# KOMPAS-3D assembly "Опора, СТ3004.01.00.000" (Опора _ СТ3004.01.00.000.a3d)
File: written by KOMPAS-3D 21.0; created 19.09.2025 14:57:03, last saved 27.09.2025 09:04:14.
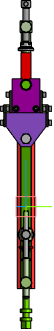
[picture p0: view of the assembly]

Document properties: Полное имя файла: C:\Users\Lutik\Yandex.Disk\Документы\Новая папка\Стапель №2\Стапель _ СТ3004.00.00.000\Опора _ СТ3004.01.00.000\3D\Опора _ СТ3004.01.00.000.a3d; Автор: 1

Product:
- Part/product: Опора  | designation СТ3004.01.00.000
    Масса: 19.478308
    Форматы листов документа: A3
  - Component [assembly]: Кронштейн  | designation СТ3004.01.01.000  | pos. 2  | Масса: 11.762936; Форматы листов документа: A2; source file: ..\2D\Кронштейн _ СТ3004.01.01.000\Кронштейн _ СТ3004.01.01.000.cdw, Кронштейн _ СТ3004.01.01.000\Кронштейн _ СТ3004.01.01.000.a3d
  - Component [assembly]: Кронштейн  | designation СТ3004.01.02.000  | pos. 3  | Масса: 5.184451; Форматы листов документа: A3; source file: ..\2D\Кронштейн _ СТ3004.01.02.000\Кронштейн _ СТ3004.01.02.000.cdw, Кронштейн _ СТ3004.01.02.000\Кронштейн _ СТ3004.01.02.000.a3d
  - Component [detail]: Винт  | designation СТ3003.01.00.001  | pos. 4  | Материал: Круг$d30 ГОСТ 2590-2006;Ст3сп ГОСТ 535-2005$ (density 7850 kg/m3); Масса: 0.303608; Форматы листов документа: A4; additional columns: 120; source file: ..\..\..\Стапель _ СТ3003.00.00.000\Опора _ СТ3003.01.00.000\2D\Винт _ СТ3003.01.00.001.cdw, ..\..\..\Стапель _ СТ3003.00.00.000\Опора _ СТ3003.01.00.000\3D\Винт _ СТ3003.01.00.001.m3d
  - Component [assembly]: Струбцина  | designation СТ3003.01.03.000  | pos. 1  | Масса: 1.103282; Раздел спецификации: Сборочные единицы; Форматы листов документа: A3; source file: ..\..\..\Стапель _ СТ3003.00.00.000\Опора _ СТ3003.01.00.000\2D\Струбцина _ СТ3003.01.03.000\Струбцина _ СТ3003.01.03.000.cdw, ..\..\..\Стапель _ СТ3003.00.00.000\Опора _ СТ3003.01.00.000\3D\Струбцина _ СТ3003.01.03.000\Струбцина _ СТ3003.01.03.000.a3d
  - Component [assembly]: Струбцина  | designation СТ3003.01.03.000-02  | pos. 1  | Масса: 1.075052; Форматы листов документа: A3; source file: ..\..\..\Стапель _ СТ3003.00.00.000\Опора _ СТ3003.01.00.000\2D\Струбцина _ СТ3003.01.03.000\Струбцина _ СТ3003.01.03.000.cdw, ..\..\..\Стапель _ СТ3003.00.00.000\Опора _ СТ3003.01.00.000\3D\Струбцина _ СТ3003.01.03.000\Струбцина _ СТ3003.01.03.000.a3d
  - Component [standard]: Винт с шестигранной головкой ГОСТ Р ИСО 4017-М16 x 45-5.8-A2P  | pos. 5  | Материал: Сталь (density 1000 kg/m3); Масса: 0.01392; Раздел спецификации: Стандартные изделия; Рассекать на разрезах: no; additional columns: ГОСТ Р ИСО 4017-2013; М16 x 45 - 5.8 - A2P

Referenced files in C:\Users\1\Yandex.Disk\Документы\Новая папка\Стапель №2\Стапель _ СТ3003.00.00.000\Опора _ СТ3003.01.00.000\3D\Струбцина _ СТ3003.01.03.000\: Струбцина _ СТ3003.01.03.000.a3d
Referenced files in C:\Users\1\Yandex.Disk\Документы\Новая папка\Стапель №2\Стапель _ СТ3004.00.00.000\Опора _ СТ3004.01.00.000\3D\Кронштейн _ СТ3004.01.02.000\: Кронштейн _ СТ3004.01.02.000.a3d
Referenced files in C:\Users\1\Yandex.Disk\Документы\Новая папка\Стапель №2\Стапель _ СТ3003.00.00.000\Опора _ СТ3003.01.00.000\3D\: Винт _ СТ3003.01.00.001.m3d
Referenced files in C:\Users\1\Yandex.Disk\Документы\Новая папка\Стапель №2\Стапель _ СТ3004.00.00.000\Опора _ СТ3004.01.00.000\3D\Кронштейн _ СТ3004.01.01.000\: Кронштейн _ СТ3004.01.01.000.a3d
Referenced files in C:\Users\Lutik\Yandex.Disk\Документы\Новая папка\Стапель №2\Стапель _ СТ3004.00.00.000\Опора _ СТ3004.01.00.000\3D\Кронштейн _ СТ3004.01.01.000\: Кронштейн _ СТ3004.01.01.000.a3d
Referenced files in C:\Users\Lutik\Yandex.Disk\Документы\Новая папка\Стапель №2\Стапель _ СТ3004.00.00.000\Опора _ СТ3004.01.00.000\2D\Кронштейн _ СТ3004.01.01.000\: Кронштейн _ СТ3004.01.01.000.cdw
Referenced files in C:\Users\Lutik\Yandex.Disk\Документы\Новая папка\Стапель №2\Стапель _ СТ3004.00.00.000\Опора _ СТ3004.01.00.000\3D\Кронштейн _ СТ3004.01.02.000\: Кронштейн _ СТ3004.01.02.000.a3d
Referenced files in C:\Users\Lutik\Yandex.Disk\Документы\Новая папка\Стапель №2\Стапель _ СТ3004.00.00.000\Опора _ СТ3004.01.00.000\2D\Кронштейн _ СТ3004.01.02.000\: Кронштейн _ СТ3004.01.02.000.cdw
Referenced files in C:\Users\Lutik\Yandex.Disk\Документы\Новая папка\Стапель №2\Стапель _ СТ3003.00.00.000\Опора _ СТ3003.01.00.000\3D\: Винт _ СТ3003.01.00.001.m3d
Referenced files in C:\Users\Lutik\Yandex.Disk\Документы\Новая папка\Стапель №2\Стапель _ СТ3003.00.00.000\Опора _ СТ3003.01.00.000\2D\: Винт _ СТ3003.01.00.001.cdw
Referenced files in C:\Users\Lutik\Yandex.Disk\Документы\Новая папка\Стапель №2\Стапель _ СТ3003.00.00.000\Опора _ СТ3003.01.00.000\3D\Струбцина _ СТ3003.01.03.000\: Струбцина _ СТ3003.01.03.000.a3d
Referenced files in C:\Users\Lutik\Yandex.Disk\Документы\Новая папка\Стапель №2\Стапель _ СТ3003.00.00.000\Опора _ СТ3003.01.00.000\2D\Струбцина _ СТ3003.01.03.000\: Струбцина _ СТ3003.01.03.000.cdw
Referenced files in C:\Program Files\ASCON\KOMPAS-3D v21\Libs\PartLib\DATA\VAULT\Methods\Kompas\3D\: PLib_Bolt_1_ISO_1100.m3d
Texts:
  СТ3003.01.03.000
  СТ3004.01.02.000
  СТ3003.01.00.001
  СТ3004.01.01.000
  СТ3003.01.03.000 - 02
  СТ3003.01.03.000-02
  Винт с шестигранной головкой
  ГОСТ Р ИСО
  СТ3004.01.00.000
  СТ3004.01.01.000 Кронштейн
  СТ3004.01.02.000 Кронштейн
  СТ3003.01.00.001 Винт
  СТ3003.01.03.000 Струбцина
  СТ3003.01.03.000-02 Струбцина
  hole1
  hole2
